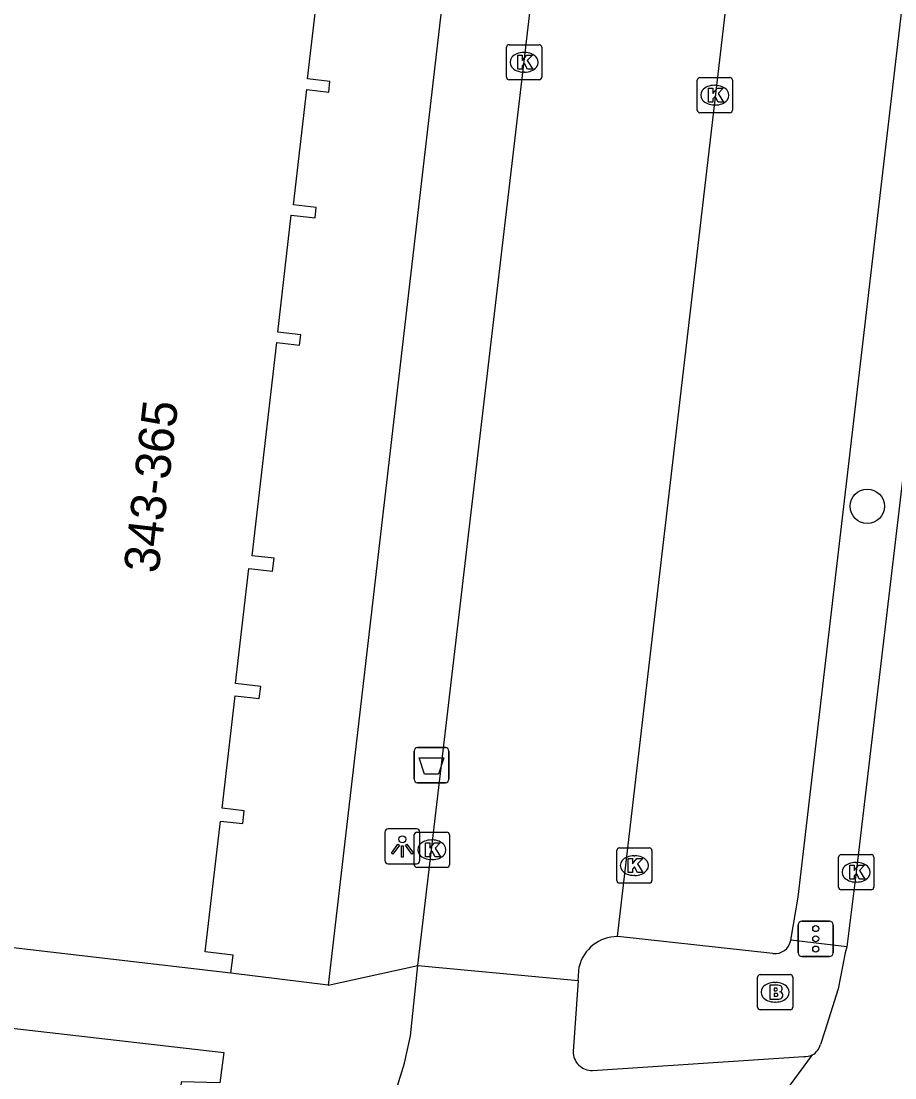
# Model space of a CAD drawing. Extents: x 160861 to 161308, y 384024 to 384878.
# Drawn here: x 161203.22 to 161228.08, y 384304.92 to 384334.96 of the extents above; entities that cross this region are included whole.
import ezdxf

# ---------------------------------------------------------------- set-up
doc = ezdxf.new("R2010")
doc.units = 0
for name, color, linetype in [('IMGEO_Afvalbak', 7, 'Continuous'), ('IMGEO_Boom', 7, 'Continuous'), ('IMGEO_Brandkraan', 7, 'Continuous'), ('IMGEO_Fietspad_gesloten', 7, 'Continuous'), ('IMGEO_Kolk', 7, 'Continuous'), ('IMGEO_Lichtpunt', 7, 'Continuous'), ('IMGEO_Pand', 7, 'Continuous'), ('IMGEO_Pand_nummerreeks', 7, 'Continuous'), ('IMGEO_Parkeervlak_open', 7, 'Continuous'), ('IMGEO_Rijbaan_lokaal_gesloten', 7, 'Continuous'), ('IMGEO_Rijbaan_lokaal_open', 7, 'Continuous'), ('IMGEO_Verkeersregelinstallatiepaal', 7, 'Continuous'), ('IMGEO_Voetpad_open', 7, 'Continuous')]:
    doc.layers.add(name, color=color, linetype=linetype)

msp = doc.modelspace()

# ---------------------------------------------------------------- linework, layer by layer
at = {"layer": 'IMGEO_Afvalbak'}
for p, q in [((161214.501, 384314.309), (161215.291, 384314.309)), ((161215.291, 384314.309), (161214.501, 384314.309)), ((161214.401, 384313.409), (161214.401, 384314.209)), ((161214.401, 384314.209), (161214.401, 384313.409)), ((161215.391, 384314.209), (161215.391, 384313.409)), ((161215.391, 384313.409), (161215.391, 384314.209)), ((161215.291, 384313.309), (161214.501, 384313.309)), ((161214.501, 384313.309), (161215.291, 384313.309))]:
    msp.add_line(p, q, dxfattribs=at)
msp.add_lwpolyline([(161214.544, 384314.023), (161215.248, 384314.023), (161215.099, 384313.553), (161214.693, 384313.553), (161214.544, 384314.023)], dxfattribs=at)
for centre, start, end in [((161214.501, 384314.209), 90, 180), ((161214.501, 384314.209), 90, 180), ((161215.291, 384314.209), 0, 90), ((161215.291, 384314.209), 360, 90), ((161214.501, 384313.409), 180, 270), ((161214.501, 384313.409), 180, 270), ((161215.291, 384313.409), 270, 0), ((161215.291, 384313.409), 270, 0)]:
    msp.add_arc(centre, 0.1, start, end, dxfattribs=at)
at = {"layer": 'IMGEO_Boom'}
msp.add_circle((161227.29, 384321.171), 0.489, dxfattribs=at)
at = {"layer": 'IMGEO_Brandkraan'}
for p, q in [((161224.171, 384306.928), (161224.171, 384307.78)), ((161224.246, 384307.854), (161225.098, 384307.854)), ((161225.172, 384307.78), (161225.172, 384306.928)), ((161224.659, 384307.634), (161224.684, 384307.634)), ((161225.098, 384306.854), (161224.246, 384306.854)), ((161224.682, 384307.074), (161224.657, 384307.074))]:
    msp.add_line(p, q, dxfattribs=at)
for points in [[(161224.171, 384306.928), (161224.171, 384307.78)], [(161224.246, 384307.854), (161225.098, 384307.854)], [(161225.172, 384307.78), (161225.172, 384306.928)], [(161224.519, 384307.554), (161224.519, 384307.154), (161224.732, 384307.154)], [(161224.75, 384307.554), (161224.519, 384307.554)], [(161224.698, 384307.473), (161224.644, 384307.473), (161224.644, 384307.397)], [(161224.644, 384307.397), (161224.697, 384307.397)], [(161224.706, 384307.321), (161224.644, 384307.321), (161224.644, 384307.24)], [(161224.644, 384307.24), (161224.706, 384307.24)], [(161225.098, 384306.854), (161224.246, 384306.854)]]:
    msp.add_lwpolyline(points, dxfattribs=at)
for centre, radius, start, end in [((161224.248, 384307.778), 0.0765, 91.552, 178.448), ((161224.248, 384307.778), 0.0765, 91.552, 178.448), ((161225.096, 384307.778), 0.0765, 1.552, 88.448), ((161225.096, 384307.778), 0.0765, 1.552, 88.448), ((161224.699, 384307.435), 0.0379, 267.8285, 90.9355), ((161224.754, 384307.409), 0.145, 59.4692, 91.5367), ((161224.779, 384307.456), 0.0922, 285.5137, 58.1501), ((161224.707, 384307.28), 0.0404, 269.8759, 90.5077), ((161224.738, 384307.405), 0.251, 268.6676, 293.5347), ((161224.784, 384307.264), 0.105, 301.3115, 78.989), ((161224.248, 384306.93), 0.0765, 181.552, 268.448), ((161224.248, 384306.93), 0.0765, 181.552, 268.448), ((161225.096, 384306.93), 0.0765, 271.552, 358.448), ((161225.096, 384306.93), 0.0765, 271.552, 358.448)]:
    msp.add_arc(centre, radius, start, end, dxfattribs=at)
for centre, major_axis, ratio, start_param, end_param in [((161224.658, 384307.354), (-0.387, 0.002), 0.722429, 4.712389, 7.853982), ((161224.683, 384307.354), (-0.39, 0.002), 0.717154, 1.570796, 4.712389)]:
    msp.add_ellipse(centre, major_axis=major_axis, ratio=ratio, start_param=start_param, end_param=end_param, dxfattribs=at)
at = {"layer": 'IMGEO_Fietspad_gesloten'}
for points in [[(161213.891, 384304.57), (161214.131, 384305.339), (161214.302, 384306.115), (161214.509, 384308.114)], [(161219.067, 384307.692), (161218.921, 384305.669)], [(161219.475, 384305.132), (161225.483, 384305.524)]]:
    msp.add_lwpolyline(points, dxfattribs=at)
for centre, radius, start, end in [((161219.458, 384305.669), 0.537, 180.0195, 271.7659), ((161225.52, 384305.972), 0.449, 265.2897, 297.148)]:
    msp.add_arc(centre, radius, start, end, dxfattribs=at)
at = {"layer": 'IMGEO_Kolk'}
for p, q in [((161217.029, 384333.369), (161217.029, 384334.221)), ((161217.104, 384334.295), (161217.956, 384334.295)), ((161218.03, 384334.221), (161218.03, 384333.369)), ((161217.517, 384334.075), (161217.542, 384334.075)), ((161217.956, 384333.295), (161217.104, 384333.295)), ((161217.54, 384333.515), (161217.515, 384333.515)), ((161222.455, 384332.434), (161222.455, 384333.286)), ((161222.53, 384333.36), (161223.382, 384333.36)), ((161223.456, 384333.286), (161223.456, 384332.434)), ((161222.943, 384333.14), (161222.968, 384333.14)), ((161223.382, 384332.36), (161222.53, 384332.36)), ((161222.966, 384332.58), (161222.941, 384332.58)), ((161214.48, 384311.904), (161215.332, 384311.904)), ((161214.405, 384310.978), (161214.405, 384311.83)), ((161214.893, 384311.684), (161214.918, 384311.684)), ((161215.406, 384311.83), (161215.406, 384310.978)), ((161220.165, 384310.529), (161220.165, 384311.381)), ((161220.24, 384311.455), (161221.092, 384311.455)), ((161221.166, 384311.381), (161221.166, 384310.529)), ((161214.916, 384311.124), (161214.891, 384311.124)), ((161220.653, 384311.235), (161220.678, 384311.235)), ((161226.474, 384310.34), (161226.474, 384311.192)), ((161226.549, 384311.266), (161227.401, 384311.266)), ((161226.962, 384311.046), (161226.987, 384311.046)), ((161227.475, 384311.192), (161227.475, 384310.34)), ((161215.332, 384310.904), (161214.48, 384310.904)), ((161221.092, 384310.455), (161220.24, 384310.455)), ((161220.676, 384310.675), (161220.651, 384310.675)), ((161226.985, 384310.486), (161226.96, 384310.486)), ((161227.401, 384310.266), (161226.549, 384310.266))]:
    msp.add_line(p, q, dxfattribs=at)
for points in [[(161217.029, 384333.369), (161217.029, 384334.221)], [(161217.104, 384334.295), (161217.956, 384334.295)], [(161218.03, 384334.221), (161218.03, 384333.369)], [(161217.35, 384333.995), (161217.473, 384333.995), (161217.473, 384333.844), (161217.603, 384333.995), (161217.767, 384333.995), (161217.621, 384333.844), (161217.774, 384333.595), (161217.622, 384333.595), (161217.537, 384333.759), (161217.473, 384333.692), (161217.473, 384333.595), (161217.35, 384333.595), (161217.35, 384333.995)], [(161217.956, 384333.295), (161217.104, 384333.295)], [(161222.455, 384332.434), (161222.455, 384333.286)], [(161222.53, 384333.36), (161223.382, 384333.36)], [(161223.456, 384333.286), (161223.456, 384332.434)], [(161222.776, 384333.06), (161222.899, 384333.06), (161222.899, 384332.909), (161223.029, 384333.06), (161223.193, 384333.06), (161223.047, 384332.909), (161223.2, 384332.66), (161223.048, 384332.66), (161222.963, 384332.824), (161222.899, 384332.757), (161222.899, 384332.66), (161222.776, 384332.66), (161222.776, 384333.06)], [(161223.382, 384332.36), (161222.53, 384332.36)], [(161214.48, 384311.904), (161215.332, 384311.904)], [(161214.405, 384310.978), (161214.405, 384311.83)], [(161214.726, 384311.604), (161214.849, 384311.604), (161214.849, 384311.453), (161214.979, 384311.604), (161215.143, 384311.604), (161214.997, 384311.453), (161215.15, 384311.204), (161214.998, 384311.204), (161214.913, 384311.368), (161214.849, 384311.301), (161214.849, 384311.204), (161214.726, 384311.204), (161214.726, 384311.604)], [(161215.406, 384311.83), (161215.406, 384310.978)], [(161220.165, 384310.529), (161220.165, 384311.381)], [(161220.24, 384311.455), (161221.092, 384311.455)], [(161221.166, 384311.381), (161221.166, 384310.529)], [(161220.486, 384311.155), (161220.609, 384311.155), (161220.609, 384311.004), (161220.739, 384311.155), (161220.903, 384311.155), (161220.757, 384311.004), (161220.91, 384310.755), (161220.758, 384310.755), (161220.673, 384310.919), (161220.609, 384310.852), (161220.609, 384310.755), (161220.486, 384310.755), (161220.486, 384311.155)], [(161226.474, 384310.34), (161226.474, 384311.192)], [(161226.549, 384311.266), (161227.401, 384311.266)], [(161227.475, 384311.192), (161227.475, 384310.34)], [(161215.332, 384310.904), (161214.48, 384310.904)], [(161226.795, 384310.966), (161226.918, 384310.966), (161226.918, 384310.815), (161227.048, 384310.966), (161227.212, 384310.966), (161227.066, 384310.815), (161227.219, 384310.566), (161227.067, 384310.566), (161226.982, 384310.73), (161226.918, 384310.663), (161226.918, 384310.566), (161226.795, 384310.566), (161226.795, 384310.966)], [(161221.092, 384310.455), (161220.24, 384310.455)], [(161227.401, 384310.266), (161226.549, 384310.266)]]:
    msp.add_lwpolyline(points, dxfattribs=at)
for centre, start, end in [((161217.106, 384334.219), 91.552, 178.448), ((161217.106, 384334.219), 91.552, 178.448), ((161217.954, 384334.219), 1.552, 88.448), ((161217.954, 384334.219), 1.552, 88.448), ((161217.106, 384333.371), 181.552, 268.448), ((161217.106, 384333.371), 181.552, 268.448), ((161217.954, 384333.371), 271.552, 358.448), ((161217.954, 384333.371), 271.552, 358.448), ((161222.532, 384333.284), 91.552, 178.448), ((161222.532, 384333.284), 91.552, 178.448), ((161223.38, 384333.284), 1.552, 88.448), ((161223.38, 384333.284), 1.552, 88.448), ((161222.532, 384332.436), 181.552, 268.448), ((161222.532, 384332.436), 181.552, 268.448), ((161223.38, 384332.436), 271.552, 358.448), ((161223.38, 384332.436), 271.552, 358.448), ((161214.482, 384311.828), 91.552, 178.448), ((161214.482, 384311.828), 91.552, 178.448), ((161215.33, 384311.828), 1.552, 88.448), ((161215.33, 384311.828), 1.552, 88.448), ((161220.242, 384311.379), 91.552, 178.448), ((161220.242, 384311.379), 91.552, 178.448), ((161221.09, 384311.379), 1.552, 88.448), ((161221.09, 384311.379), 1.552, 88.448), ((161226.551, 384311.19), 91.552, 178.448), ((161226.551, 384311.19), 91.552, 178.448), ((161227.399, 384311.19), 1.552, 88.448), ((161227.399, 384311.19), 1.552, 88.448), ((161214.482, 384310.98), 181.552, 268.448), ((161214.482, 384310.98), 181.552, 268.448), ((161215.33, 384310.98), 271.552, 358.448), ((161215.33, 384310.98), 271.552, 358.448), ((161220.242, 384310.531), 181.552, 268.448), ((161220.242, 384310.531), 181.552, 268.448), ((161221.09, 384310.531), 271.552, 358.448), ((161221.09, 384310.531), 271.552, 358.448), ((161226.551, 384310.342), 181.552, 268.448), ((161226.551, 384310.342), 181.552, 268.448), ((161227.399, 384310.342), 271.552, 358.448), ((161227.399, 384310.342), 271.552, 358.448)]:
    msp.add_arc(centre, 0.0765, start, end, dxfattribs=at)
for centre, major_axis, ratio, start_param, end_param in [((161217.516, 384333.795), (-0.387, 0.002), 0.722429, 4.712389, 7.853982), ((161217.541, 384333.795), (-0.39, 0.002), 0.717154, 1.570796, 4.712389), ((161222.942, 384332.86), (-0.387, 0.002), 0.722429, 4.712389, 7.853982), ((161222.967, 384332.86), (-0.39, 0.002), 0.717154, 1.570796, 4.712389), ((161214.892, 384311.404), (-0.387, 0.002), 0.722429, 4.712389, 7.853982), ((161214.917, 384311.404), (-0.39, 0.002), 0.717154, 1.570796, 4.712389), ((161220.652, 384310.955), (-0.387, 0.002), 0.722429, 4.712389, 7.853982), ((161220.677, 384310.955), (-0.39, 0.002), 0.717154, 1.570796, 4.712389), ((161226.961, 384310.766), (-0.387, 0.002), 0.722429, 4.712389, 7.853982), ((161226.986, 384310.766), (-0.39, 0.002), 0.717154, 1.570796, 4.712389)]:
    msp.add_ellipse(centre, major_axis=major_axis, ratio=ratio, start_param=start_param, end_param=end_param, dxfattribs=at)
at = {"layer": 'IMGEO_Lichtpunt'}
for p, q in [((161213.568, 384311.904), (161213.568, 384311.097)), ((161213.568, 384311.904), (161213.568, 384311.097)), ((161214.47, 384311.999), (161213.662, 384311.999)), ((161214.47, 384311.999), (161213.662, 384311.999)), ((161214.564, 384311.097), (161214.564, 384311.904)), ((161214.564, 384311.097), (161214.564, 384311.904)), ((161213.662, 384311.003), (161214.47, 384311.003)), ((161213.662, 384311.003), (161214.47, 384311.003))]:
    msp.add_line(p, q, dxfattribs=at)
for points in [[(161213.942, 384311.568), (161213.981, 384311.54), (161213.793, 384311.278), (161213.755, 384311.305), (161213.942, 384311.568)], [(161214.044, 384311.52), (161214.091, 384311.52), (161214.091, 384311.198), (161214.044, 384311.198), (161214.044, 384311.52)], [(161214.154, 384311.54), (161214.192, 384311.567), (161214.379, 384311.305), (161214.34, 384311.277), (161214.154, 384311.54)]]:
    msp.add_lwpolyline(points, dxfattribs=at)
msp.add_circle((161214.067, 384311.702), 0.0994, dxfattribs=at)
for centre, start, end in [((161213.662, 384311.904), 90, 180), ((161213.662, 384311.904), 90, 180), ((161214.47, 384311.904), 0, 90), ((161214.47, 384311.904), 0, 90), ((161213.662, 384311.097), 180, 270), ((161213.662, 384311.097), 180, 270), ((161214.47, 384311.097), 270, 0), ((161214.47, 384311.097), 270, 360)]:
    msp.add_arc(centre, 0.0946, start, end, dxfattribs=at)
at = {"layer": 'IMGEO_Pand'}
for points in [[(161209.191, 384307.893), (161209.251, 384308.411), (161208.459, 384308.503), (161208.891, 384312.222), (161209.528, 384312.148), (161209.57, 384312.515), (161208.938, 384312.588), (161209.309, 384315.782), (161209.998, 384315.702), (161210.038, 384316.045), (161209.319, 384316.129), (161209.699, 384319.403), (161210.374, 384319.325), (161210.417, 384319.693), (161209.793, 384319.765), (161210.497, 384325.823), (161211.145, 384325.748), (161211.18, 384326.047), (161210.522, 384326.123), (161210.908, 384329.448), (161211.583, 384329.369), (161211.618, 384329.67), (161210.966, 384329.745), (161211.346, 384333.018), (161211.973, 384332.945), (161212.008, 384333.247), (161211.372, 384333.321), (161211.796, 384336.977)], [(161209.191, 384307.893), (161195.993, 384309.427), (161196.025, 384309.707)]]:
    msp.add_lwpolyline(points, dxfattribs=at)
at = {"layer": 'IMGEO_Parkeervlak_open'}
msp.add_lwpolyline([(161225.116, 384308.834), (161225.325, 384310.055), (161229.745, 384347.857), (161230.065, 384350.609)], dxfattribs=at)
at = {"layer": 'IMGEO_Rijbaan_lokaal_gesloten'}
for points in [[(161232.221, 384354.922), (161231.358, 384347.709), (161230.903, 384343.902), (161229.318, 384330.573), (161226.975, 384310.766), (161226.705, 384308.649)], [(161226.705, 384308.649), (161226.66, 384308.475), (161226.465, 384307.452), (161226.083, 384306.244), (161225.956, 384305.864)], [(161225.725, 384305.572), (161223.239, 384302.198)]]:
    msp.add_lwpolyline(points, dxfattribs=at)
msp.add_arc((161225.518, 384305.973), 0.451, 297.273, 346.0323, dxfattribs=at)
at = {"layer": 'IMGEO_Rijbaan_lokaal_open'}
for points in [[(161214.509, 384308.114), (161215.229, 384314.215), (161219.587, 384351.336), (161220.201, 384356.33)], [(161220.186, 384308.937), (161225.169, 384351.658)], [(161214.509, 384308.114), (161219.067, 384307.692)], [(161219.067, 384307.692), (161219.093, 384308.082)]]:
    msp.add_lwpolyline(points, dxfattribs=at)
msp.add_arc((161220.186, 384307.811), 1.126, 89.9791, 166.0896, dxfattribs=at)
at = {"layer": 'IMGEO_Verkeersregelinstallatiepaal'}
for p, q in [((161225.328, 384308.473), (161225.328, 384309.273)), ((161225.328, 384309.273), (161225.328, 384308.473)), ((161225.428, 384309.373), (161226.218, 384309.373)), ((161226.218, 384309.373), (161225.428, 384309.373)), ((161226.318, 384309.273), (161226.318, 384308.473)), ((161226.318, 384308.473), (161226.318, 384309.273)), ((161226.218, 384308.373), (161225.428, 384308.373)), ((161225.428, 384308.373), (161226.218, 384308.373))]:
    msp.add_line(p, q, dxfattribs=at)
for centre in [(161225.823, 384309.163), (161225.823, 384308.873), (161225.823, 384308.583)]:
    msp.add_circle(centre, 0.085, dxfattribs=at)
for centre, start, end in [((161225.428, 384309.273), 90, 180), ((161225.428, 384309.273), 90, 180), ((161226.218, 384309.273), 0, 90), ((161226.218, 384309.273), 360, 90), ((161225.428, 384308.473), 180, 270), ((161225.428, 384308.473), 180, 270), ((161226.218, 384308.473), 270, 0), ((161226.218, 384308.473), 270, 0)]:
    msp.add_arc(centre, 0.1, start, end, dxfattribs=at)
at = {"layer": 'IMGEO_Voetpad_open'}
for points in [[(161218.761, 384366.2), (161211.956, 384307.552)], [(161224.605, 384308.454), (161220.199, 384308.936), (161220.186, 384308.937)], [(161226.705, 384308.649), (161225.116, 384308.834)], [(161211.956, 384307.552), (161214.509, 384308.114)], [(161211.956, 384307.552), (161209.191, 384307.893)], [(161193.029, 384304.59), (161193.135, 384307.46), (161208.985, 384305.639), (161208.876, 384304.774), (161207.771, 384304.807), (161207.639, 384302.974), (161208.64, 384302.912), (161208.399, 384301.003), (161205.958, 384300.995)]]:
    msp.add_lwpolyline(points, dxfattribs=at)
msp.add_arc((161224.659, 384308.915), 0.464, 263.3516, 349.9204, dxfattribs=at)

# ---------------------------------------------------------------- texts
at = {"layer": 'IMGEO_Pand_nummerreeks'}
msp.add_text('343-365', height=1, rotation=83.3735, dxfattribs=at).set_placement((161207.129, 384319.243))

doc.saveas('drawing.dxf')
